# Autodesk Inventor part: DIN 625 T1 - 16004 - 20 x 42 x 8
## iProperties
Created: 2006-02
Part Number: DIN 625 T1 - 16004 - 20 x 42 x 8
Material: Steel, Mild
Description: Deep Groove Ball Bearing
Document SubType Name: Modeling
Standard: DIN 625 T1
Designer: Andy Moles
Standards Organization: DIN
Language: en-US
Size Designation: 16004 - 20 x 42 x 8
Categories: <MemberInstance><Categories><Category DisplayName="Shaft Parts" InternalName="7f7aeb1f-a693-4053-b835-cee3144e0d98" Mnemonic="SHFT"><Category DisplayName="Beari
Density: 1 g/cm^3
Author: Andy Moles
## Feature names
1. Body [Revolution]
2. Fillet1
3. Ball [Revolution]
4. Balls [Circular Pattern]
